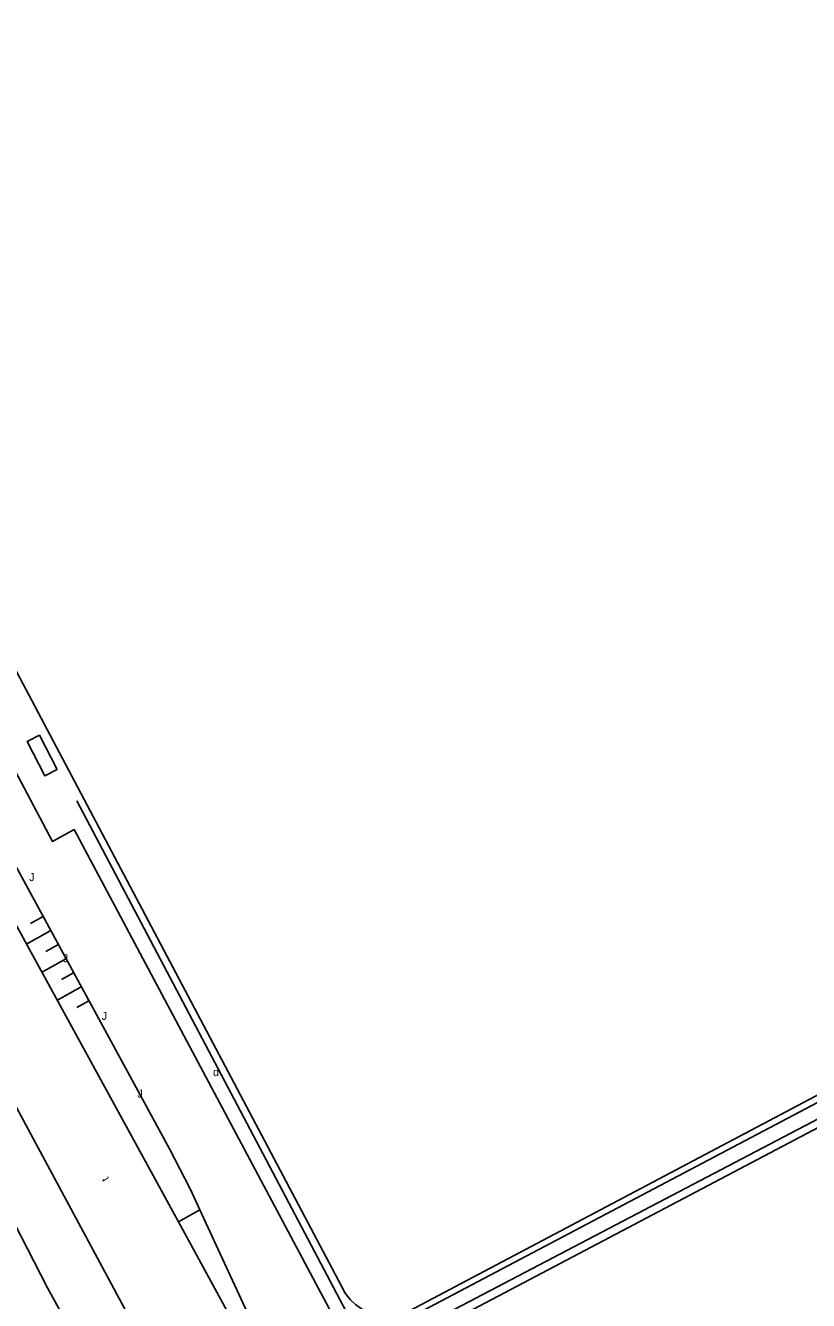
# Model space of a CAD drawing. Extents: x 134999 to 136502, y 457398 to 459002.
# Drawn here: x 136111.8 to 136160.8, y 457621.4 to 457701.1 of the extents above; entities that cross this region are included whole.
import ezdxf

# ---------------------------------------------------------------- set-up
doc = ezdxf.new("R2010")
doc.units = 0
for name, color, linetype in [('RI_DGTB_18', 7, 'Continuous'), ('RI_DGTB_29', 7, 'Continuous'), ('RI_DGTB_31', 7, 'Continuous'), ('RI_DGTB_43', 7, 'Continuous'), ('RI_DGTB_48', 7, 'Continuous'), ('RI_DGTB_49', 7, 'Continuous'), ('RI_DGTB_55', 7, 'Continuous'), ('RI_DGTB_58', 7, 'Continuous'), ('RI_DGTB_6', 7, 'Continuous')]:
    doc.layers.add(name, color=color, linetype=linetype)

msp = doc.modelspace()

# ---------------------------------------------------------------- linework, layer by layer
at = {"layer": 'RI_DGTB_18'}
for p, q in [((136112.154, 457644.94), (136112.905, 457645.355)), ((136111.871, 457643.641), (136113.388, 457644.479)), ((136113.121, 457643.189), (136113.872, 457643.604)), ((136112.838, 457641.89), (136114.355, 457642.728)), ((136114.088, 457641.438), (136114.839, 457641.853)), ((136113.805, 457640.139), (136115.322, 457640.977)), ((136115.055, 457639.687), (136115.806, 457640.102)), ((136128.415, 457614.798), (136122.744, 457627.053))]:
    msp.add_line(p, q, dxfattribs=at)
for points in [[(136063.968, 457736.473), (136078.546, 457708.97), (136080.695, 457704.886), (136101.064, 457667.235), (136120.849, 457630.867), (136122.138, 457628.364), (136122.744, 457627.053)], [(136123.733, 457602.393), (136120.854, 457608.26), (136113.226, 457622.174), (136108.621, 457631.115), (136104.943, 457638.994), (136101.264, 457646.446), (136083.989, 457678.217), (136077.85, 457689.911), (136077.399, 457690.806), (136074.236, 457697.397), (136072.278, 457700.64), (136071.067, 457702.994), (136069.704, 457704.875), (136065.561, 457709.646), (136062.974, 457712.597), (136061.189, 457715.009), (136060.471, 457716.789), (136060.125, 457718.639), (136060.201, 457718.837), (136061.046, 457719.422)]]:
    msp.add_lwpolyline(points, dxfattribs=at)
at = {"layer": 'RI_DGTB_48'}
msp.add_line((136122.744, 457627.053), (136121.392, 457626.305), dxfattribs=at)
msp.add_lwpolyline([(136199.877, 457656.368), (136197.799, 457654.906), (136199.269, 457652.172), (136128.657, 457614.944), (136128.415, 457614.798)], dxfattribs=at)
at = {"layer": 'RI_DGTB_49'}
msp.add_lwpolyline([(136179.214, 457685.457), (136196.623, 457652.376), (136132.905, 457618.765), (136115.046, 457652.608)], dxfattribs=at)
at = {"layer": 'RI_DGTB_55'}
for points in [[(136196.949, 457655.273), (136198.574, 457652.238), (136132.548, 457617.637), (136114.894, 457650.812), (136113.527, 457650.075), (136097.454, 457680.477), (136098.843, 457681.226), (136081.172, 457714.844)], [(136193.021, 457650.992), (136136.179, 457620.934), (136135.798, 457620.721), (136135.33, 457620.544), (136134.839, 457620.443), (136134.338, 457620.422), (136133.841, 457620.48), (136133.359, 457620.617), (136132.905, 457620.829), (136132.49, 457621.11), (136132.125, 457621.453), (136131.82, 457621.85), (136131.581, 457622.291), (136084.467, 457711.393)]]:
    msp.add_lwpolyline(points, dxfattribs=at)
at = {"layer": 'RI_DGTB_58'}
for p, q in [((136102.393, 457649.868), (136126.134, 457605.889)), ((136121.392, 457626.305), (136127.863, 457614.463))]:
    msp.add_line(p, q, dxfattribs=at)
msp.add_lwpolyline([(136121.392, 457626.305), (136098.946, 457667.306), (136079.053, 457703.844), (136061.812, 457735.294)], dxfattribs=at)
at = {"layer": 'RI_DGTB_6'}
msp.add_line((136112.723, 457656.711), (136113.826, 457654.561), dxfattribs=at)
msp.add_lwpolyline([(136112.723, 457656.711), (136111.955, 457656.318), (136113.058, 457654.167), (136113.826, 457654.561)], dxfattribs=at)

# ---------------------------------------------------------------- texts
at = {"layer": 'RI_DGTB_29'}
msp.add_text('d', height=0.5, dxfattribs=at).set_placement((136123.56, 457635.409))
at = {"layer": 'RI_DGTB_31'}
for p in [(136112.072, 457647.591), (136114.182, 457642.521), (136116.602, 457638.921), (136118.832, 457634.071)]:
    msp.add_text('J', height=0.5, dxfattribs=at).set_placement(p)
at = {"layer": 'RI_DGTB_43'}
msp.add_text('t', height=0.5, rotation=118.30993, dxfattribs=at).set_placement((136117.079, 457628.987))

doc.saveas('drawing.dxf')
